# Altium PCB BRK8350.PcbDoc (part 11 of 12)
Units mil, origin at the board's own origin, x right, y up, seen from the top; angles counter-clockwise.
Board outline 9448.82 x 5905.51 mil, 8 copper layers (L1-TOP, L2-GND, L3-SIG, L4-GND, L5-PWR, L6-PWR, L7-GND, L8-BOT), stack 57.69 mil thick; 288 components, 543 nets, 1891 pads, 2032 vias.
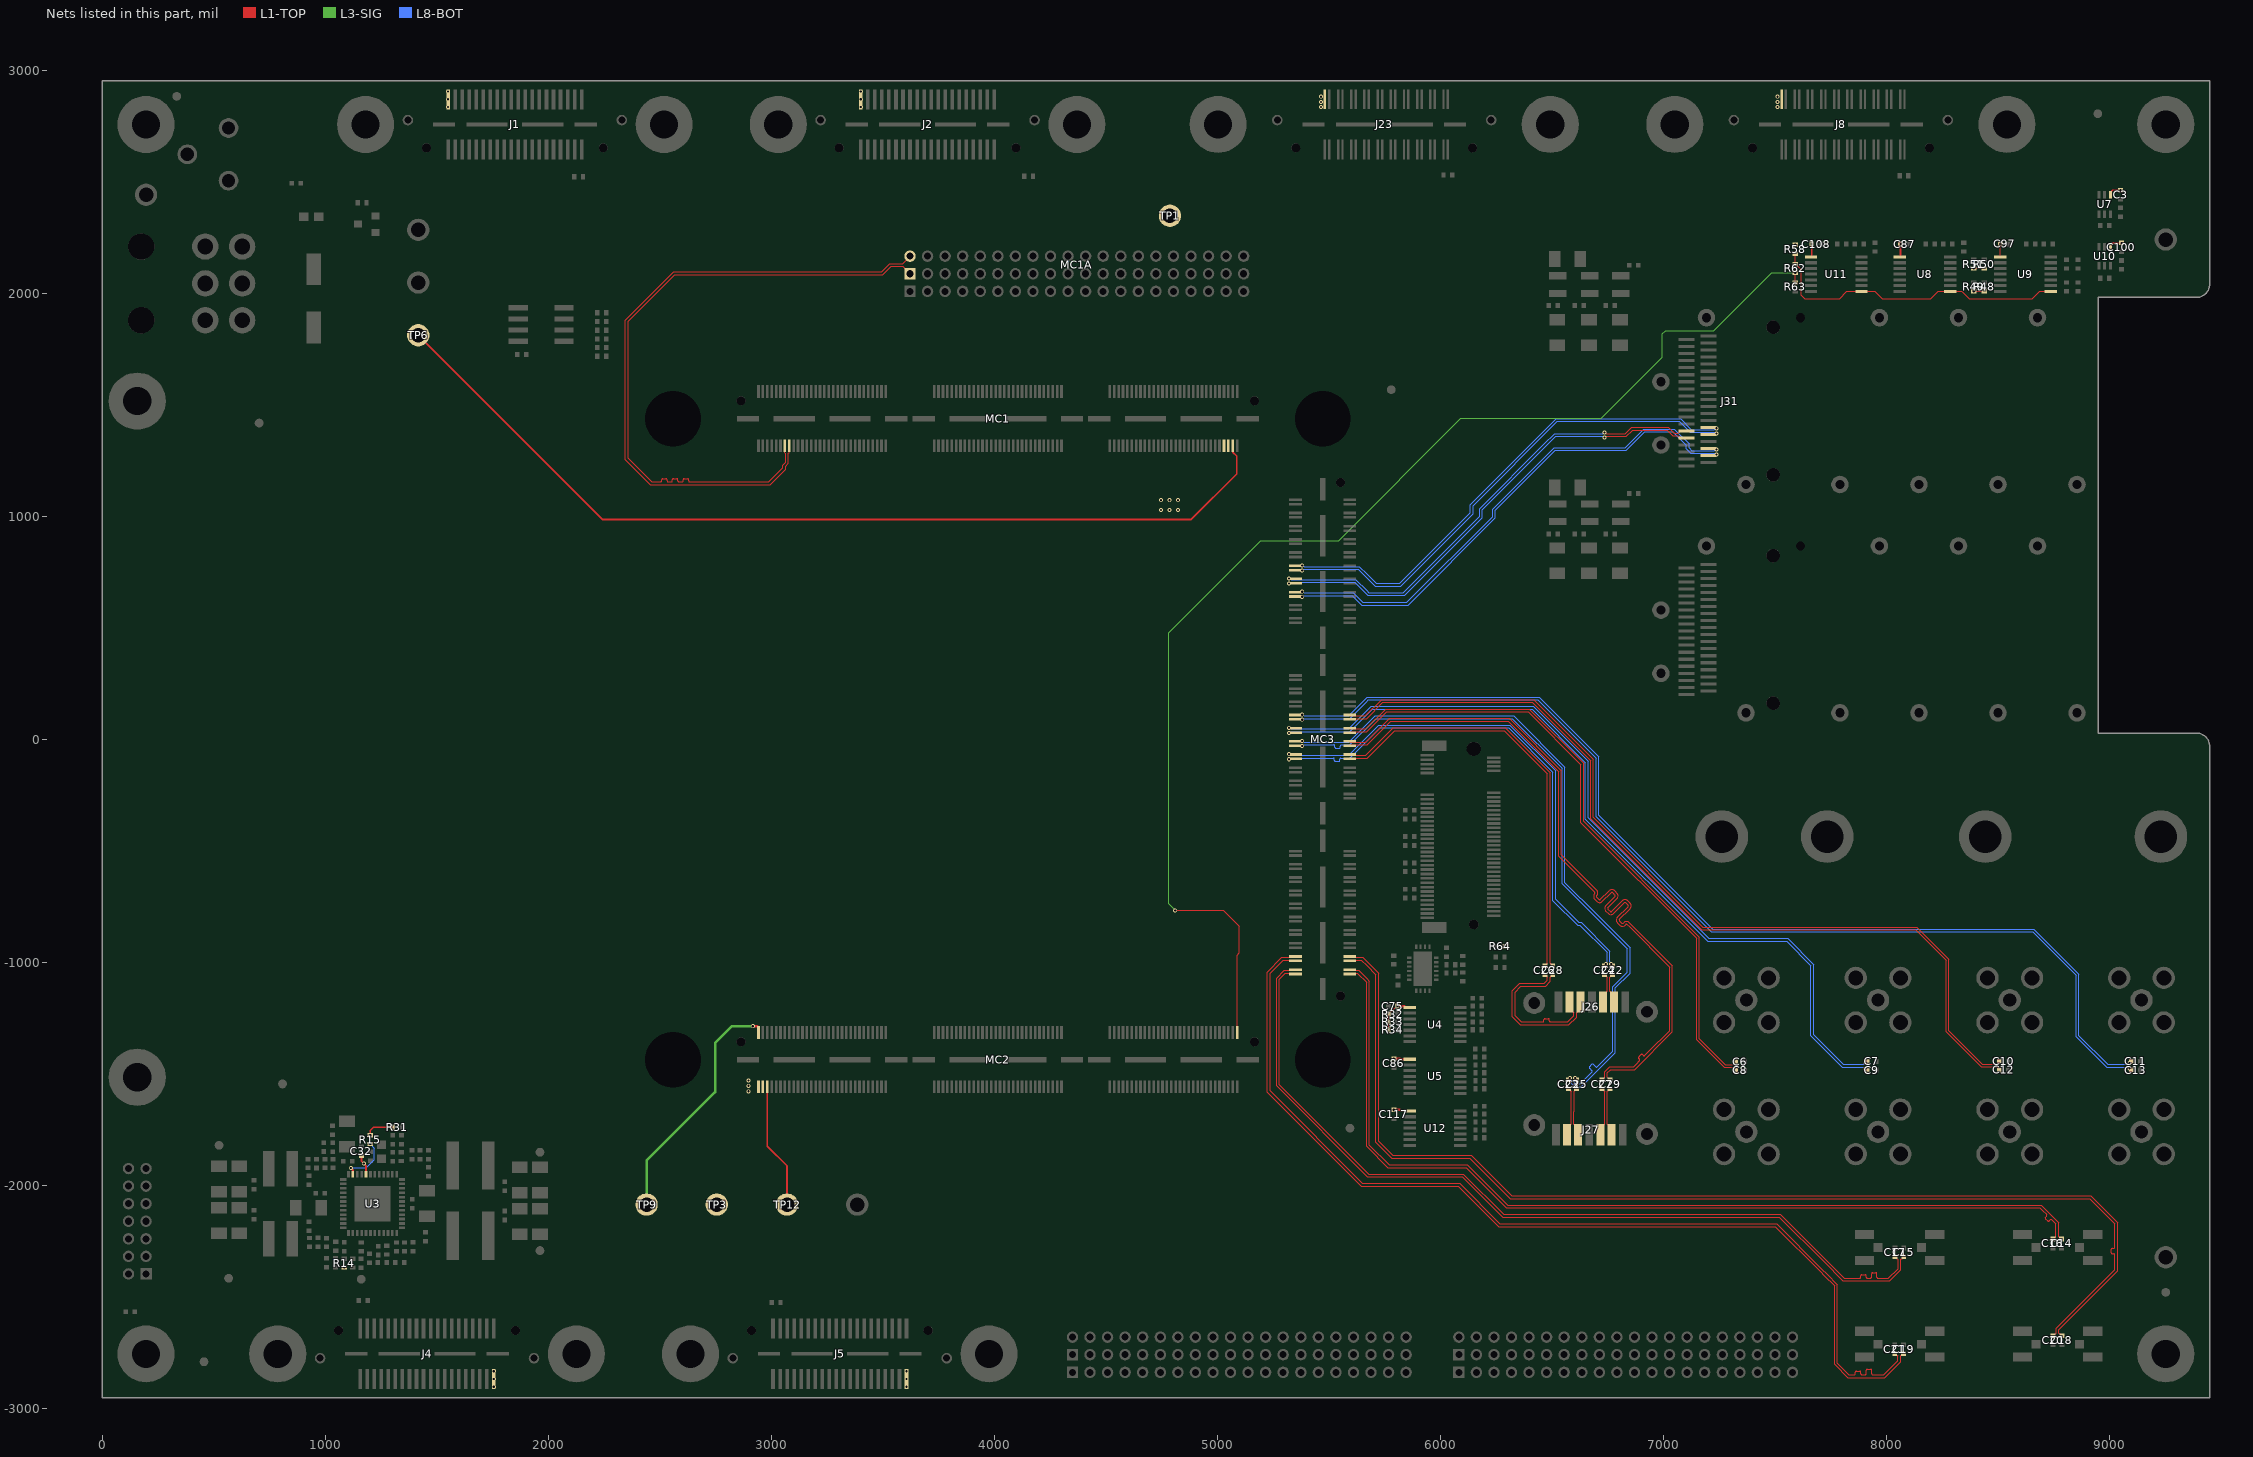
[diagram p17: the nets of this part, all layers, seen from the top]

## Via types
v1: diameter 18, hole 10, L1-TOP to L8-BOT, tented both sides, 2032 vias

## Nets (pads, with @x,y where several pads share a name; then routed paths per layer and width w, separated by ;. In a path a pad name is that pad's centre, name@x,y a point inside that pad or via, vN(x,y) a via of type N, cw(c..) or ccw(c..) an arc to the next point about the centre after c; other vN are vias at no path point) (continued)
QSFP_2_TX2N: J31.2 MC3.32 | length 2270.6
  L8-BOT w4.2: v1(5380.17,638.28) 5383.91,638.28 5388.95,643.32 5604.51,643.32 5646.95,600.88 5855.09,600.88 6246.95,992.73 6246.95,1026.21 6515.22,1294.49 6833.86,1294.49 6917.32,1377.95 7042.75,1377.95 7102.5,1318.21 7102.5,1301.41 7122.81,1281.1 7228.34,1281.1 7233.68,1275.76 v1(7237.42,1275.76)
QSFP_2_TX2P: J31.3 MC3.30 | length 2270.6
  L8-BOT w4.2: v1(5380.17,660.96) 5383.91,660.96 5388.95,655.92 5609.73,655.92 5652.17,613.48 5849.87,613.48 6234.35,997.95 6234.35,1031.43 6510,1307.09 6828.64,1307.09 6912.1,1390.55 7047.97,1390.55 7115.1,1323.43 7115.1,1306.63 7128.03,1293.7 7228.34,1293.7 7233.68,1299.05 v1(7237.42,1299.05)
QSFP_2_TX3N: J31.34 MC3.28 | length 2155.9
  L1-TOP w4.2: v1(6736.22,1352.53) 6739.14,1352.53 6744.09,1357.48 6833.86,1357.48 6862.2,1385.83 7016.61,1385.83 7042.6,1359.84 7067.34,1359.84 7069.8,1357.38 7069.8,1355.18 7074.59,1350.39 J31.34@7103.13,1350.39
  L8-BOT w4.2: v1(5321.43,697.33) 5325.17,697.33 5330.21,702.38 5616.32,702.38 5669.29,649.4 5674.51,644.18 5839.29,644.18 6188.26,993.16 6188.26,1028.65 6517.09,1357.48 6727.54,1357.48 6732.49,1352.53 v1(6736.22,1352.53)
QSFP_2_TX3P: J31.33 MC3.26 | length 2155.9
  L1-TOP w4.2: v1(6736.22,1375.03) 6739.14,1375.03 6744.09,1370.08 6828.64,1370.08 6856.99,1398.43 7021.83,1398.43 7047.82,1372.44 7067.34,1372.44 7069.8,1374.9 7069.8,1377.1 7074.59,1381.89 J31.33@7103.13,1381.89
  L8-BOT w4.2: v1(5321.43,720.02) 5325.17,720.02 5330.21,714.98 5621.54,714.98 5669.29,667.22 5679.73,656.78 5834.07,656.78 6175.66,998.38 6175.66,1033.87 6465.12,1323.33 6511.87,1370.08 6727.54,1370.08 6732.49,1375.03 v1(6736.22,1375.03)
QSFP_2_TX4N: J31.5 MC3.24 | length 2239.7
  L8-BOT w4.2: v1(5380.17,756.39) 5383.91,756.39 5388.95,761.43 5632.07,761.43 5669.29,724.21 5707.51,685.98 5821.97,685.98 6146.46,1010.47 6146.46,1045.96 6524.9,1424.41 7071.66,1424.41 7120.47,1375.59 7228.34,1375.59 7233.68,1370.24 v1(7237.42,1370.24)
QSFP_2_TX4P: J31.6 MC3.22 | length 2239.7
  L8-BOT w4.2: v1(5380.17,779.07) 5383.91,779.07 5388.95,774.03 5637.28,774.03 5669.29,742.03 5712.73,698.58 5816.75,698.58 6133.86,1015.69 6133.86,1051.18 6519.69,1437.01 7076.87,1437.01 7125.69,1388.19 7228.34,1388.19 7233.68,1393.54 v1(7237.42,1393.54)
QSFP_THREESTATE#: R58.1 R62.2 U8.8 U9.8 U11.8 | length 1393.5
  L1-TOP w5: R58.1@7590.55,2177.17 R62.2@7590.55,2129.92 7592.52,2129.92 7617.49,2104.95 7617.49,1990.78 7633.86,1974.41 7789.37,1974.41 7822.83,2007.87 U11.8@7887.8,2007.87 7947.43,2007.87 7980.89,1974.41 8198.82,1974.41 8232.28,2007.87 U8.8@8285.43,2007.87 8338.58,2007.87 8372.05,1974.41 8653.54,1974.41 8687.01,2007.87 U9.8@8736.22,2007.87
QSFP_THREESTATE_N_IO: MC2.179 R62.1 R63.2 | length 5635.9
  L1-TOP w5: v1(4811.02,-767.72) 5027.06,-767.72 5098.43,-839.09 5098.43,-958.37 5088.6,-968.19 5088.6,-1240.16 MC2.179@5088.6,-1315.34 ; R63.2@7590.55,2047.24 v1(7590.55,2090.55)
  L3-SIG w5: v1(4811.02,-767.72) 4782.17,-738.86 4782.17,477.84 5194.09,889.76 5544.24,889.76 6092.29,1437.81 6720.98,1437.81 6995.26,1712.09 6995.26,1816.92 7009.37,1831.03 7225.91,1831.03 7485.43,2090.55 v1(7590.55,2090.55)
SATA_1_RXB+: C28.2 MC3.65 | length 1905.5
  L1-TOP w4.2: MC3.65@5594.11,-68.88 5597.65,-72.42 5665.78,-72.42 5789.25,51.05 6291.41,51.05 6300.32,42.14 6492.52,-150.06 6492.52,-989.23 6492.52,-1005.45 6494.98,-1007.91 6495.8,-1007.91 C28.2@6503.94,-1016.05
SATA_1_RXB+_C: C28.1 J26.6 | length 696.2
  L1-TOP w4.2: C28.1@6503.94,-1056.2 6495.8,-1064.34 6494.98,-1064.34 6492.52,-1066.8 6492.52,-1086.49 6471.67,-1107.33 6361.17,-1107.33 6334.65,-1133.86 6334.65,-1240.16 6362.2,-1267.72 6420.67,-1267.72 6459.5,-1267.72 ccw(c6459.5,-1262.88) 6464.34,-1262.88 6464.34,-1257.68 cw(c6469.18,-1257.68) 6469.18,-1252.84 6483.7,-1252.84 cw(c6483.7,-1257.68) 6488.54,-1257.68 6488.54,-1262.88 ccw(c6493.38,-1262.88) 6493.38,-1267.72 6519.69,-1267.72 6570.87,-1267.72 6597.64,-1240.95 6597.64,-1226.74 6595.18,-1224.28 6594.55,-1224.28 6578.94,-1208.66 J26.6@6578.94,-1179.13
SATA_1_RXB-: C26.2 MC3.67 | length 1884.6
  L1-TOP w4.2: MC3.67@5594.11,-88.57 5597.65,-85.02 5671,-85.02 5794.47,38.45 6286.19,38.45 6479.92,-155.28 6479.92,-876.28 6479.92,-984.01 6479.92,-1005.45 6477.46,-1007.91 6476.64,-1007.91 C26.2@6468.5,-1016.05
SATA_1_RXB-_C: C26.1 J26.5 | length 716.5
  L1-TOP w4.2: C26.1@6468.5,-1056.2 6476.64,-1064.34 6477.46,-1064.34 6479.92,-1066.8 6479.92,-1081.27 6466.45,-1094.73 6355.95,-1094.73 6322.05,-1128.64 6322.05,-1245.38 6356.99,-1280.32 6576.09,-1280.32 6610.24,-1246.16 6610.24,-1226.74 6612.7,-1224.28 6613.32,-1224.28 6628.94,-1208.66 J26.5@6628.94,-1179.13
SATA_1_TXA+: C22.2 MC3.66 | length 2313.4
  L8-BOT w4.2: v1(5321.43,-67.38) 5325.17,-67.38 5330.21,-72.42 5574.1,-72.42 5589.11,-72.42 5724.38,62.84 6311.11,62.84 6320.02,53.93 6516.54,-142.58 6516.54,-663.78 6516.54,-718.31 6620.08,-821.85 6631.01,-821.85 6760.04,-950.88 6760.04,-998.66 6765.74,-1004.36 v1(6765.74,-1008.02)
SATA_1_TXA+_C: C22.1 J26.2 | length 138.2
  L1-TOP w4.2: C22.1@6773.74,-1054.24 6760.24,-1067.74 6760.24,-1130.62 6778.94,-1149.32 J26.2@6778.94,-1179.13
SATA_1_TXA-: C24.2 MC3.68 | length 2314.1
  L8-BOT w4.2: v1(5321.43,-90.07) 5325.17,-90.07 5330.21,-85.02 5493.94,-85.02 5520.24,-85.02 cw(c5520.24,-89.86) 5525.08,-89.86 5525.08,-95.16 ccw(c5529.92,-95.16) 5529.92,-100 5544.44,-100 ccw(c5544.44,-95.16) 5549.28,-95.16 5549.28,-89.86 cw(c5554.12,-89.86) 5554.12,-85.02 5574.1,-85.02 5594.33,-85.02 5729.6,50.24 6305.9,50.24 6503.94,-147.8 6503.94,-723.53 6614.86,-834.45 6625.79,-834.45 6747.44,-956.1 6747.44,-998.66 6741.74,-1004.36 v1(6741.74,-1008.02)
SATA_1_TXA-_C: C24.1 J26.3 | length 138.4
  L1-TOP w4.2: J26.3@6728.94,-1179.13 6728.94,-1148.93 6747.64,-1130.23 6747.64,-1068.13 C24.1@6733.74,-1054.24
SATA_2_RXB+: C29.2 MC3.61 | length 3198.4
  L1-TOP w4.2: MC3.61@5594.11,-9.83 5597.65,-13.37 5665.72,-13.37 5771.94,92.85 6308.73,92.85 6317.64,83.94 6542.59,-141.01 6542.59,-518.97 6680.67,-657.05 6700.56,-676.94 ; 6700.58,-676.96 6702.41,-678.78 6702.41,-679.11 cw(c6688.23,-689.27) 6700.56,-701.6 ccw(c6703.98,-705.03) 6700.56,-708.45 6710.83,-718.72 ccw(c6714.25,-715.29) 6717.67,-718.71 6756.5,-679.89 cw(c6768.83,-692.22) 6778.99,-678.04 6779.32,-678.04 6781.14,-679.86 ; C29.2@6760.45,-1527.17 6752.31,-1519.03 6751.49,-1519.03 6749.03,-1516.57 6749.03,-1507.48 6749.03,-1496.06 6763.99,-1481.1 6871.36,-1481.1 7040.16,-1312.31 7040.16,-1016.54 6852.36,-828.74 6846.42,-822.8 6844.58,-820.95 6844.25,-820.95 ccw(c6834.09,-835.13) 6821.76,-822.8 6819.83,-824.72 cw(c6816.41,-821.3) 6812.99,-824.72 6802.72,-814.46 cw(c6806.15,-811.03) 6802.7,-807.63 6850.31,-760.02 ccw(c6837.98,-747.69) 6852.16,-737.54 6852.15,-737.21 6850.33,-735.38 6840.04,-725.09 ; 6781.16,-679.89 6791.43,-690.15 ; 6791.45,-690.18 6793.28,-692 6793.28,-692.33 cw(c6779.1,-702.49) 6791.43,-714.82 6750.66,-755.59 ccw(c6754.1,-758.99) 6750.68,-762.41 6760.95,-772.68 ccw(c6764.37,-769.26) 6767.79,-772.68 6815.35,-725.12 ; 6815.38,-725.09 cw(c6827.71,-737.43) 6837.87,-723.25 6838.2,-723.25 6840.02,-725.07
SATA_2_RXB+_C: C29.1 J27.6 | length 219.7
  L1-TOP w4.2: C29.1@6760.45,-1567.32 6752.31,-1575.46 6751.49,-1575.46 6749.03,-1577.92 6749.03,-1639.75 6748.82,-1639.96 6748.82,-1726.02 6751.28,-1728.48 6751.9,-1728.48 6767.52,-1744.09 J27.6@6767.52,-1773.62
SATA_2_RXB-: C27.2 MC3.63 | length 3197.6
  L1-TOP w4.2: MC3.63@5594.11,-29.51 5597.65,-25.97 5670.94,-25.97 5777.16,80.25 6303.51,80.25 6529.99,-146.23 6529.99,-524.19 6671.76,-665.96 6691.62,-685.82 cw(c6688.23,-689.27) 6691.65,-692.69 6691.61,-692.74 ccw(c6703.98,-705.03) 6691.65,-717.36 6701.92,-727.62 ccw(c6714.25,-715.29) 6726.58,-727.62 6765.41,-688.8 cw(c6768.83,-692.22) 6772.27,-688.82 6782.49,-699.03 ; C27.2@6725.01,-1527.17 6733.15,-1519.03 6733.97,-1519.03 6736.43,-1516.57 6736.43,-1502.26 6736.43,-1490.84 6758.77,-1468.5 6866.14,-1468.5 6882.63,-1452.01 6892.47,-1442.18 ccw(c6889.04,-1438.76) 6892.47,-1435.33 6889.12,-1431.99 cw(c6892.55,-1428.57) 6889.12,-1425.15 6899.39,-1414.88 cw(c6902.81,-1418.3) 6906.24,-1414.88 6909.58,-1418.22 ccw(c6913,-1414.8) 6916.42,-1418.22 6935.02,-1399.62 7027.56,-1307.09 7027.56,-1021.76 6843.45,-837.65 6837.55,-831.74 ; 6741.77,-746.66 ccw(c6754.1,-758.99) 6741.77,-771.32 6752.04,-781.59 ccw(c6764.37,-769.26) 6776.7,-781.59 6824.31,-733.98 cw(c6827.71,-737.43) 6831.15,-734.02 6841.37,-744.24 cw(c6837.98,-747.69) 6841.4,-751.12 6793.84,-798.68 ccw(c6806.15,-811.03) 6793.81,-823.37 6804.08,-833.63 ccw(c6816.41,-821.3) 6828.74,-833.63 6830.67,-831.71 cw(c6834.09,-835.13) 6837.53,-831.73 ; 6741.8,-746.63 6782.52,-705.91 ccw(c6779.1,-702.49) 6782.5,-699.04
SATA_2_RXB-_C: C27.1 J27.5 | length 219.7
  L1-TOP w4.2: J27.5@6717.52,-1773.62 6717.52,-1744.09 6733.14,-1728.48 6733.76,-1728.48 6736.22,-1726.02 6736.22,-1634.74 6736.43,-1634.53 6736.43,-1577.92 6733.97,-1575.46 6733.15,-1575.46 C27.1@6725.01,-1567.32
SATA_2_TXA+: C23.2 MC3.62 | length 3046.2
  L8-BOT w4.2: v1(5380.17,-8.33) 5383.91,-8.33 5388.95,-13.37 5582.5,-13.37 5589.05,-13.37 5707.06,104.64 6328.43,104.64 6337.34,95.73 6558.34,-125.27 6558.34,-642.88 6701.44,-785.98 6841.48,-926.03 6850.39,-934.94 6850.39,-1049.32 6784.25,-1115.46 6784.25,-1405.51 6631.85,-1557.92 6601.84,-1557.92 6586.02,-1542.1 6586.02,-1528.49 6580.32,-1522.79 v1(6580.32,-1519.13)
SATA_2_TXA+_C: C23.1 J27.2 | length 219.7
  L1-TOP w4.2: J27.2@6567.52,-1773.62 6567.52,-1744.09 6583.14,-1728.48 6583.76,-1728.48 6586.22,-1726.02 6586.22,-1664.28 6586.43,-1664.07 6586.43,-1577.92 6583.97,-1575.46 6583.15,-1575.46 C23.1@6575.01,-1567.32
SATA_2_TXA-: C25.2 MC3.64 | length 3045.9
  L8-BOT w4.2: v1(5380.17,-31.01) 5383.91,-31.01 5388.95,-25.97 5496.06,-25.97 5522.36,-25.97 cw(c5522.36,-30.81) 5527.2,-30.81 5527.2,-35.87 ccw(c5532.04,-35.87) 5532.04,-40.71 5546.56,-40.71 ccw(c5546.56,-35.87) 5551.4,-35.87 5551.4,-30.81 cw(c5556.24,-30.81) 5556.24,-25.97 5582.5,-25.97 5594.27,-25.97 5712.28,92.04 6323.21,92.04 6545.74,-130.49 6545.74,-648.1 6696.22,-798.58 6837.79,-940.16 6837.79,-1044.1 6771.65,-1110.24 6771.65,-1400.29 6721.8,-1450.15 6703.2,-1468.74 cw(c6699.78,-1465.32) 6696.36,-1468.74 6685.73,-1458.12 ccw(c6682.31,-1461.54) 6678.89,-1458.12 6668.62,-1468.39 ccw(c6672.04,-1471.81) 6668.62,-1475.23 6679.25,-1485.86 cw(c6675.82,-1489.28) 6679.25,-1492.7 6670.62,-1501.33 6626.63,-1545.32 6607.06,-1545.32 6598.62,-1536.88 6598.62,-1528.49 6604.32,-1522.79 v1(6604.32,-1519.13)
SATA_2_TXA-_C: C25.1 J27.3 | length 219.7
  L1-TOP w4.2: C25.1@6610.45,-1567.32 6602.31,-1575.46 6601.49,-1575.46 6599.03,-1577.92 6599.03,-1669.29 6598.82,-1669.5 6598.82,-1726.02 6601.28,-1728.48 6601.9,-1728.48 6617.52,-1744.09 J27.3@6617.52,-1773.62
SMA_RXN0: C8.2 MC3.59 | length 2855
  L1-TOP w4.2: MC3.59@5594.11,29.54 5597.65,33.09 5670.88,33.09 5759.84,122.05 6394.08,122.05 6629.92,-113.79 6629.92,-374.02 7148.82,-892.91 7148.82,-1347.74 7272.96,-1471.88 7314.11,-1471.88 7316.57,-1474.35 7316.57,-1476.95 C8.2@7324.7,-1485.08
SMA_RXN1: C12.2 MC3.55 | length 3968.3
  L1-TOP w4.2: MC3.55@5594.11,88.6 5597.65,92.14 5669.02,92.14 5741.59,164.72 6412.33,164.72 6673,-95.95 6673,-356.17 7171.95,-855.12 8130.71,-855.12 8266.93,-991.34 8266.93,-1312.72 8423.91,-1469.71 8495.59,-1469.71 8498.05,-1472.17 8498.05,-1474.78 C12.2@8506.18,-1482.91
SMA_RXP0: C6.2 MC3.57 | length 2855
  L1-TOP w4.2: MC3.57@5594.11,49.23 5597.65,45.69 5665.66,45.69 5754.62,134.65 6399.3,134.65 6642.52,-108.57 6642.52,-368.8 7161.42,-887.69 7161.42,-1342.52 7278.18,-1459.28 7314.11,-1459.28 7316.57,-1456.82 7316.57,-1454.22 C6.2@7324.7,-1446.08
SMA_RXP1: C10.2 MC3.53 | length 3968.3
  L1-TOP w4.2: MC3.53@5594.11,108.28 5597.65,104.74 5663.8,104.74 5736.38,177.32 6417.55,177.32 6685.6,-90.73 6685.6,-350.95 7177.17,-842.52 8135.93,-842.52 8279.53,-986.12 8279.53,-1307.51 8429.13,-1457.11 8495.59,-1457.11 8498.05,-1454.65 8498.05,-1452.05 C10.2@8506.18,-1443.91
SMA_TXN0: C9.2 MC3.60 | length 3628.1
  L8-BOT w4.2: v1(5321.43,28.04) 5325.17,28.04 5330.21,33.09 5594.21,33.09 5694.97,133.84 6410.89,133.84 6649.61,-104.87 6649.61,-358.12 7197.79,-906.3 7551.97,-906.3 7661.42,-1015.75 7661.42,-1330.71 7801.48,-1470.77 7883.32,-1470.77 7897.06,-1470.77 7902.32,-1476.02 v1(7906.05,-1476.02)
SMA_TXN1: C13.2 MC3.56 | length 4745.6
  L8-BOT w4.2: v1(5380.17,87.1) 5383.91,87.1 5388.95,92.14 5594.21,92.14 5669.29,167.22 5669.29,167.28 5677.66,175.64 6437.32,175.64 6697.85,-84.89 6697.85,-347.25 7215.11,-864.5 8655.84,-864.5 8850.39,-1059.06 8850.39,-1334.65 8986.51,-1470.77 9067.05,-1470.77 9080.79,-1470.77 9086.05,-1476.02 v1(9089.78,-1476.02)
SMA_TXP0: C7.2 MC3.58 | length 3628.1
  L8-BOT w4.2: v1(5321.43,50.73) 5325.17,50.73 5330.21,45.69 5588.99,45.69 5689.75,146.44 6416.11,146.44 6662.21,-99.65 6662.21,-352.9 7203.01,-893.7 7557.19,-893.7 7674.02,-1010.53 7674.02,-1325.49 7806.69,-1458.17 7888.54,-1458.17 7897.06,-1458.17 7902.32,-1452.91 v1(7906.05,-1452.91)
SMA_TXP1: C11.2 MC3.54 | length 4745.6
  L8-BOT w4.2: v1(5380.17,109.78) 5383.91,109.78 5388.95,104.74 5588.99,104.74 5656.69,172.44 5656.69,172.5 5672.44,188.24 6442.54,188.24 6710.45,-79.67 6710.45,-342.03 7220.32,-851.9 8661.06,-851.9 8862.99,-1053.84 8862.99,-1329.43 8991.73,-1458.17 9072.27,-1458.17 9080.79,-1458.17 9086.05,-1452.91 v1(9089.78,-1452.91)
SUPPLY_1_CE: R15.1 U3.23 | length 231.9
  L1-TOP w8: v1(1114.74,-1922.66) 1124.16,-1932.08 U3.23@1124.16,-1950.77
  L8-BOT w5: v1(1114.74,-1922.66) 1183.51,-1922.66 1220.91,-1885.26 1220.91,-1833.67 v1(1202.1,-1814.85)
UFL_RXN0: C16.2 MC3.119 | length 4162.6
  L1-TOP w4.2: MC3.119@5594.11,-1053.13 5597.65,-1049.59 5628.33,-1049.59 5669.29,-1090.55 5669.29,-1824.96 5764.87,-1920.54 6115.26,-1920.54 6296.36,-2101.64 8688.26,-2101.64 8699.1,-2112.48 8717.7,-2131.08 cw(c8714.27,-2134.5) 8717.7,-2137.93 8712.81,-2142.81 ccw(c8716.23,-2146.24) 8712.81,-2149.66 8723.08,-2159.93 ccw(c8726.5,-2156.5) 8729.92,-2159.93 8734.81,-2155.04 cw(c8738.23,-2158.46) 8741.65,-2155.04 8755.91,-2169.29 8759.42,-2172.8 8759.42,-2230.48 8756.96,-2232.94 8754.17,-2232.94 C16.2@8746.03,-2241.08
UFL_RXN1: C20.2 MC3.115 | length 5001.9
  L1-TOP w4.2: MC3.115@5594.11,-994.08 5597.65,-990.54 5645.95,-990.54 5669.29,-1013.88 5711.09,-1055.68 5711.09,-1807.65 5782.18,-1878.74 6132.58,-1878.74 6313.68,-2059.84 8911.09,-2059.84 9023.62,-2172.38 9023.62,-2251.97 9023.62,-2278.27 cw(c9018.78,-2278.27) 9018.78,-2283.11 9012.87,-2283.11 ccw(c9012.87,-2287.95) 9008.03,-2287.95 9008.03,-2302.47 ccw(c9012.87,-2302.47) 9012.87,-2307.31 9018.78,-2307.31 cw(c9018.78,-2312.15) 9023.62,-2312.15 9023.62,-2326.77 9023.62,-2378.67 8760.42,-2641.88 8760.42,-2647.7 8760.42,-2663.55 8757.96,-2666.01 8755.17,-2666.01 C20.2@8747.03,-2674.15
UFL_RXP0: C14.2 MC3.117 | length 4158.6
  L1-TOP w4.2: MC3.117@5594.11,-1033.45 5597.65,-1036.99 5633.55,-1036.99 5669.29,-1072.73 5681.89,-1085.33 5681.89,-1819.75 5770.09,-1907.94 6120.48,-1907.94 6301.58,-2089.04 8693.48,-2089.04 8708.01,-2103.58 8772.02,-2167.58 8772.02,-2230.48 8774.48,-2232.94 8777.27,-2232.94 C14.2@8785.4,-2241.08
UFL_RXP1: C18.2 MC3.113 | length 4999.9
  L1-TOP w4.2: MC3.113@5594.11,-974.39 5597.65,-977.94 5651.16,-977.94 5669.29,-996.06 5723.69,-1050.46 5723.69,-1802.43 5787.4,-1866.14 6137.8,-1866.14 6146.7,-1875.05 6318.9,-2047.24 8698.19,-2047.24 8916.31,-2047.24 9036.22,-2167.16 9036.22,-2251.97 9036.22,-2383.89 8773.02,-2647.1 8773.02,-2652.92 8773.02,-2663.55 8775.48,-2666.01 8778.27,-2666.01 C18.2@8786.4,-2674.15
UFL_TXN0: C17.2 MC3.120 | length 3833.3
  L1-TOP w4.2: MC3.120@5350.8,-1053.13 5347.26,-1049.59 5304.74,-1049.59 5277.89,-1076.45 5277.89,-1549.54 5678.09,-1949.74 6103.17,-1949.74 6284.27,-2130.84 7524.54,-2130.84 7810.23,-2416.53 7830.71,-2416.53 7879.61,-2416.53 ccw(c7879.61,-2411.69) 7884.45,-2411.69 7884.45,-2405.75 cw(c7889.29,-2405.75) 7889.29,-2400.91 7903.81,-2400.91 cw(c7903.81,-2405.75) 7908.65,-2405.75 7908.65,-2411.69 ccw(c7913.49,-2411.69) 7913.49,-2416.53 7928.01,-2416.53 ccw(c7928.01,-2411.69) 7932.85,-2411.69 7932.85,-2396.37 cw(c7937.69,-2396.37) 7937.69,-2391.53 7952.21,-2391.53 cw(c7952.21,-2396.37) 7957.05,-2396.37 7957.05,-2411.69 ccw(c7961.89,-2411.69) 7961.89,-2416.53 7988.19,-2416.53 8008.66,-2416.53 8051.76,-2373.44 8051.76,-2331.99 8049.29,-2329.53 8046.51,-2329.53 C17.2@8038.37,-2321.39
UFL_TXN1: C21.2 MC3.116 | length 4348.1
  L1-TOP w4.2: MC3.116@5350.8,-994.08 5347.26,-990.54 5295,-990.54 5236.09,-1049.45 5236.09,-1577.37 5650.26,-1991.54 6085.85,-1991.54 6266.96,-2172.64 7507.23,-2172.64 7710.81,-2376.22 7732.04,-2397.45 7780.32,-2445.73 7780.32,-2798.15 7831.77,-2849.6 7834.65,-2849.6 7855.99,-2849.6 ccw(c7855.99,-2844.76) 7860.83,-2844.76 7860.83,-2837.82 cw(c7865.67,-2837.82) 7865.67,-2832.98 7880.19,-2832.98 cw(c7880.19,-2837.82) 7885.03,-2837.82 7885.03,-2844.76 ccw(c7889.87,-2844.76) 7889.87,-2849.6 7904.39,-2849.6 ccw(c7904.39,-2844.76) 7909.23,-2844.76 7909.23,-2829.44 cw(c7914.07,-2829.44) 7914.07,-2824.6 7928.59,-2824.6 cw(c7928.59,-2829.44) 7933.43,-2829.44 7933.43,-2844.76 ccw(c7938.27,-2844.76) 7938.27,-2849.6 7964.57,-2849.6 7986.91,-2849.6 8050.76,-2785.76 8050.76,-2765.06 8048.29,-2762.6 8045.51,-2762.6 C21.2@8037.37,-2754.46
UFL_TXP0: C15.2 MC3.118 | length 3831.3
  L1-TOP w4.2: MC3.118@5350.8,-1033.45 5347.26,-1036.99 5299.52,-1036.99 5265.29,-1071.23 5265.29,-1554.76 5672.87,-1962.34 6097.95,-1962.34 6279.05,-2143.44 7519.33,-2143.44 7717.68,-2341.8 7805.02,-2429.13 7830.71,-2429.13 8013.88,-2429.13 8064.36,-2378.66 8064.36,-2331.99 8066.82,-2329.53 8069.6,-2329.53 C15.2@8077.74,-2321.39
UFL_TXP1: C19.2 MC3.114 | length 4344.1
  L1-TOP w4.2: MC3.114@5350.8,-974.39 5347.26,-977.94 5289.78,-977.94 5223.49,-1044.23 5223.49,-1582.58 5645.04,-2004.14 6080.63,-2004.14 6261.74,-2185.24 7502.01,-2185.24 7705.59,-2388.82 7719.44,-2402.67 7767.72,-2450.95 7767.72,-2803.37 7826.55,-2862.2 7834.65,-2862.2 7992.13,-2862.2 8063.36,-2790.98 8063.36,-2765.06 8065.82,-2762.6 8068.6,-2762.6 C19.2@8076.74,-2754.46
VCCBATT: MC2.6 TP12.1 | length 564.6
  L1-TOP w8: MC2.6@2982.3,-1558.65 2982.3,-1611.8 2982.3,-1824.82 3070.74,-1913.26 TP12.1@3070.74,-2086.61
VDDD: C32.2 R14.2 R15.2 R31.2 U3.20 | length 220.4
  L1-TOP w8: C32.2@1162.74,-1866.74 1162.74,-1891.7 1183.21,-1912.17 U3.20@1183.21,-1950.77 ; v1(1202.1,-1775.48) 1202.1,-1754.6 1216.54,-1740.16 R31.2@1303.15,-1740.16
  other v1: 1085.74,-2368.85 1172.98,-1901.93
VIO1: J1.39 J2.39 J8.39 J23.39 MC1.174 MC1.176 TP1.1
  other v1: 4746.91,1028 4785.23,1028 4823.55,1028 4746.91,1071.31 4785.23,1071.31 4823.55,1071.31 1551.24,2833.71 3401.64,2833.71 5464.68,2833.67 7511.92,2833.67 5464.68,2856.67 7511.92,2856.67 1551.24,2868.71 3401.64,2868.71 5464.68,2880.67 7511.92,2880.67 1551.24,2903.71 3401.64,2903.71
VIO2: C3.2 C75.2 C86.2 C87.2 C97.2 C100.2 C108.2 C117.2 J4.39 J5.39 MC2.2 MC2.4 R32.2 R33.2 R34.2 R48.2 R49.2 R50.2 R51.2 R58.2 R64.2 TP3.1 U4.1 U5.1 U7.1 U8.1 U9.1 U10.1 U11.1 U12.1 | length 722.3
  L1-TOP w5: R34.2@5767.72,-1303.15 R33.2@5767.72,-1267.72 5767.72,-1230.31 5774.06,-1223.97 5776.82,-1223.97 5796.62,-1204.18 5800.74,-1204.18 5807.48,-1197.44 v1(5807.48,-1196.85) ; v1(8391.5,2007.98) R48.2@8438.74,2007.98 ; v1(8391.5,2110.35) R50.2@8438.74,2110.35 ; v1(8509.21,2220.58) 8509.21,2162.05 U9.1@8509.84,2161.42
  L1-TOP w8: U11.1@7661.42,2161.42 7661.81,2161.42 7664.7,2164.31 C108.2@7664.7,2225.62 ; U8.1@8059.06,2161.42 8059.45,2161.42 8062.34,2164.31 v1(8062.34,2219.65) ; U7.1@9003.94,2440.94 9003.94,2450.79 9014.17,2461.02 v1(9049.21,2461.02)
  L1-TOP w10: v1(5791.34,-1661.02) 5818.5,-1661.02 5824.8,-1667.32 U12.1@5863.19,-1667.32 ; 5802.17,-1432.68 5819.45,-1432.68 5821.81,-1435.04 U5.1@5863.19,-1435.04 ; U10.1@9003.94,2208.66 9003.94,2218.5 9005.83,2220.39 9007.28,2220.39 9011.68,2224.8 v1(9053.15,2224.8)
  L1-TOP w11: v1(5807.48,-1196.85) 5836.61,-1196.85 5842.52,-1202.76 U4.1@5863.19,-1202.76 U4.1@5863.43,-1202.52
  other v1: 1755.94,-2903.71 3606.34,-2903.71 1755.94,-2868.71 3606.34,-2868.71 1755.94,-2833.71 3606.34,-2833.71 2897.64,-1578.74 2897.64,-1554.42 2897.64,-1530.1 5791.34,-1432.68 6287.4,-929.13 7590.55,2216.54 7664.7,2219.62
VREF1: MC1.178 TP6.1 | length 4229.5
  L1-TOP w8: TP6.1@1417.32,1811.02 2243.11,985.24 4882.87,985.24 5086.61,1188.98 5086.61,1269.54 5068.91,1287.25 MC1.178@5068.91,1315.37
VREF2: MC2.1 TP9.1 | length 1102.8
  L1-TOP w11: v1(2917.32,-1286.8) 2937.02,-1286.8 2942.93,-1292.7 MC2.1@2942.93,-1315.34
  L3-SIG w11: TP9.1@2440.94,-2086.61 2440.94,-1889.76 2748.03,-1582.68 2748.03,-1362.2 2823.44,-1286.8 v1(2917.32,-1286.8)
XADC_VN: MC1.16 MC1A.2 | length 2926.4
  L1-TOP w4.2: MC1.16@3080.72,1315.37 3080.72,1284.73 3077.18,1281.18 3077.18,1236.59 3064.5,1223.9 3064.5,1210.65 2994.79,1140.94 2458.23,1140.94 2345.67,1253.51 2345.67,1879.23 2561.71,2095.28 3494.78,2095.28 3531.79,2132.28 3588.98,2132.28 MC1A.2@3622.05,2165.35
XADC_VP: MC1.14 MC1A.1 | length 2926.4
  L1-TOP w4.2: MC1.14@3061.04,1315.37 3061.04,1284.73 3064.58,1281.18 3064.58,1241.81 3051.9,1229.12 3051.9,1215.87 2989.57,1153.54 2660.79,1153.54 2634.49,1153.54 cw(c2634.49,1158.38) 2629.65,1158.38 2629.65,1163.69 ccw(c2624.81,1163.69) 2624.81,1168.53 2610.29,1168.53 ccw(c2610.29,1163.69) 2605.45,1163.69 2605.45,1158.38 cw(c2600.61,1158.38) 2600.61,1153.54 2586.09,1153.54 cw(c2586.09,1158.38) 2581.25,1158.38 2581.25,1163.69 ccw(c2576.41,1163.69) 2576.41,1168.53 2561.89,1168.53 ccw(c2561.89,1163.69) 2557.05,1163.69 2557.05,1158.38 cw(c2552.21,1158.38) 2552.21,1153.54 2537.69,1153.54 cw(c2537.69,1158.38) 2532.85,1158.38 2532.85,1162.52 ccw(c2528.01,1162.52) 2528.01,1167.36 2513.49,1167.36 ccw(c2513.49,1162.52) 2508.65,1162.52 2508.65,1158.38 cw(c2503.81,1158.38) 2503.81,1153.54 2477.79,1153.54 2463.45,1153.54 2358.27,1258.73 2358.27,1874.02 2566.93,2082.68 3500,2082.68 3537.01,2119.68 3588.98,2119.68 MC1A.1@3622.05,2086.61
pads on no net: FID1.FID? FID2.FID? FID3.FID? FID4.FID? FID5.FID? FID6.FID? FID7.FID? FID8.FID? J1.1@1181.1,2755.91 J1.1@2519.69,2755.91 J1.37 J1.38 J1.MH J2.1@3031.5,2755.91 J2.1@4370.08,2755.91 J2.37 J2.38 J2.MH J3.12 J3.14 J4.1@787.45,-2755.91 J4.1@2126.03,-2755.91 J4.37 J4.38 J4.MH J5.1@2637.84,-2755.91 J5.1@3976.43,-2755.91 J5.37 J5.38 J5.MH J8.1@7050.89,2756.02 J8.1@8539.87,2756.02 J8.37 J8.38 J8.MH J23.1@5003.65,2756.02 J23.1@6492.63,2756.02 J23.37 J23.38 J23.MH J24.0 J26.MH J27.MH J28.3 J30.MH J31.MH J32.6 J32.8 J32.20 J32.22 J32.24 J32.26 J32.28 J32.30 J32.32 J32.34 J32.36 J32.46 J32.48 J32.56 J32.58 J32.67 J32.MH JSO1.1 JSO2.1 JSO3.1 JSO4.1 MC1.119 MC1.120 MC1.131 MC1.132 MC1.137 MC1.138 MC1.139 MC1.141 MC1.143 MC1.145 MC1.147 MC1.148 MC1.149 MC1.150 MC1.161 MC1.162 MC1.163 MC1.164 MC1.165 MC1.166 MC1.167 MC1.168 MC1.169 MC1.170 MC1.171 MC1.172 MC1.180 MC1.MH MC2.24 MC2.26 MC2.135 MC2.136 MC2.178 MC2.180 MC2.MH MC3.17 MC3.19 MC3.105 MC3.106 MC3.107 MC3.108 MC3.109 MC3.110 MC3.111 MC3.112 MC3.MH MH1.1 MH2.1 MH5.1 MH6.1 MH7.1 MH8.1 QSFP1.0 QSFP2.0 U2.2 U2.5 U2.6 U2.10 U2.12 U2.17 U2.18 U2.20 U3.13 U3.27 U3.34 U3.41 U3.44 U3.48 U4.5 U4.6 U4.9 U4.10 U5.6 U5.9 U8.6 U8.9 U9.6 U9.9 U11.6 U11.9 U12.5 U12.6 U12.9 U12.10
copper on no net:
  other v1: 3086.61,-2472.44 3016.67,-2457.47 3377.95,-1511.39 3139.61,1200.98 3178.98,1200.98 3218.36,1200.98 3159.63,1240.35 3199,1240.35 3238.37,1240.35 3283.48,1393.7 3360.38,1393.7 3438.04,1393.7 3505.94,2583.05 3568.94,2583.05 3631.94,2583.05

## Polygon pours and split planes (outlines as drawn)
DGND on L5-PWR "L4-DGND" (solid, pour order 307): 19.68,-2932.76 19.68,2932.74 9428.8,2932.74 9428.8,-2932.76
VIO2 on L5-PWR "VIO2_L05_P302" (solid, pour order 302): 1755.91,-2289.72 1692.91,-2289.72 1692.91,-2932.76 8191.31,-2932.76 8191.31,-2755.91 7344.38,-1908.99 7344.38,1143.6 7905.51,1704.72 8584.65,1704.72 9090.55,2210.63 9090.55,2500 8870.08,2500 8629.92,2259.84 7566.93,2259.84 6389.76,1082.68 6389.76,-532.93 5405.05,-1517.65 2965.65,-1517.65 2811.35,-1517.65 2344.75,-1984.25 1755.91,-1984.25
+VDCIN on L5-PWR "L6_+VDCIN" (solid, pour order 306): 0,2952.75 0,-2275.59 1740.16,-2275.59 1740.16,-216.54 2976,1019.31 2976,1525.8 2976,1709.04 2648.12,2036.92 2648.12,2155.83 2071.5,2732.44 2071.5,2952.75
VIO1 on L5-PWR "VIO1_L05_P301" (solid, pour order 301): 1444.88,2251.97 1972.44,1724.41 3877.95,1724.41 4601.38,1000.98 4956.69,1000.98 5000,1044.29 5000,1669.29 5137.8,1807.09 5610.24,1807.09 6106.3,2303.15 7188.98,2303.15 7559.06,2673.23 7559.06,2933.24 1444.88,2933.24
+3.3V_M.2 on L5-PWR "+3.3V_M.2_L05_P299" (solid, pour order 299): 2334.65,-1972.44 2804.73,-1502.35 5403.16,-1502.35 5799.21,-1106.3 5929.67,-1106.3 5980.32,-1156.95 5980.32,-1557.06 6120.1,-1696.85 6181.5,-1696.85 6199.68,-1678.66 6199.68,-1368.97 6141.84,-1311.13 6141.73,-1161.42 6201.38,-1106.88 6199.68,-965.67 6350.39,-814.96 6350.39,43.31 6271.65,122.05 2098.43,122.05 1755.91,-220.47 1755.91,-1972.44
VDDD on L5-PWR "L6_VDDD" (solid, pour order 304): 1172.98,-1746.28 1209.98,-1746.28 1356.25,-1892.56 1356.25,-2381.28 1068.98,-2381.28 1068.98,-1988.6 1172.98,-1884.6
+VDCIN on L1-TOP "NONET_L-01_P-001" (solid, pour order 339): 1051.18,2212.6 826.77,2212.6 783.46,2255.91 783.46,2555.12 732.28,2606.3 488.19,2606.3 279.53,2397.64 279.53,1645.67 354.33,1570.87 1051.18,1570.87
+1.8VDD on L1-TOP "+1.8VDD_L01_P328" (solid, pour order 328): 5061.13,1598.43 5053.73,1598.43 5053.73,1618.35 5073.17,1637.8 5114.59,1637.8 5129.92,1622.47 5129.92,1502.75 5061.13,1502.75
VIO2 on L1-TOP "NONET_L-01_P-001" (solid, pour order 335): 2972.34,-1511.7 2952.77,-1492.13 2901.57,-1492.13 2881.89,-1511.81 2881.89,-1610.24 2901.57,-1629.92 2948.82,-1629.92 2972.34,-1606.4
+VDCIN on L1-TOP "+VDCIN_L01_P331" (solid, pour order 331): 2798.92,1633.57 2977.11,1633.57 3007.89,1602.79 3007.89,1248.05 2968.5,1208.66 2759.84,1208.66 2740.16,1228.35 2740.16,1574.8
VIO1 on L1-TOP "NONET_L-01_P-001" (solid, pour order 334): 5023.64,1343.91 5055.13,1343.91 5055.13,1275.59 5062.99,1267.73 5062.99,1200.79 4870.08,1007.87 4740.16,1007.87 4728.35,1019.68 4728.35,1083.66 4739.17,1094.49 4842.54,1094.49 5023.64,1275.59 5023.64,1286.83
DGND on L1-TOP "DGND_L01_P332" (solid, pour order 332): 5911.42,-66.93 5988.19,-66.93 6043.31,-66.93 6051.18,-74.8 6051.18,-114.17 6043.31,-122.05 5996.06,-122.05 5992.13,-118.11 5911.42,-118.11
NetC104_2 on L1-TOP "NETC104_2_L01_P319" (solid, pour order 319): 6486.19,2014.66 6564.93,2014.66 6578.71,2000.88 6578.71,1874.9 6559.02,1855.21 6488.16,1855.21 6488.16,1911.31 6501.94,1925.09 6501.94,1959.54 6486.19,1975.29
NetC92_2 on L1-TOP "NETC92_2_L01_P323" (solid, pour order 323): 6486.2,991.04 6564.94,991.04 6578.72,977.26 6578.72,851.28 6559.04,831.59 6488.17,831.59 6488.17,887.69 6501.95,901.47 6501.95,935.92 6486.2,951.67
+3.3V_M.2 on L1-TOP "+3.3V_M.2_L01_P330" (solid, pour order 330): 6171.88,-846.46 6307.09,-846.46 6326.77,-826.77 6326.77,-762.58 6171.88,-762.58
+3.3V_M.2 on L1-TOP "+3.3V_M.2_L01_P329" (solid, pour order 329): 6171.88,-27.56 6307.09,-27.56 6326.77,-47.24 6326.77,-129.92 6171.88,-129.92
NetC106_2 on L1-TOP "NETC106_2_L01_P320" (solid, pour order 320): 6630.87,2014.66 6707.65,2014.66 6721.43,2000.88 6721.43,1874.9 6701.74,1855.21 6630.87,1855.21 6630.87,1911.31 6630.87,1973.32
NetC102_2 on L1-TOP "NETC102_2_L01_P321" (solid, pour order 321): 6769.65,2014.66 6846.43,2014.66 6860.2,2000.88 6860.2,1874.9 6840.52,1855.21 6769.65,1855.21 6769.65,1911.31 6769.65,1973.32
+3.3V_QSFP on L1-TOP "+3.3V_QSFP_L01_P322" (solid, pour order 322): 6486.19,2046.16 6848.39,2046.16 6848.39,2094.39 6862.17,2108.17 6862.17,2168.2 6833.63,2196.75 6584.61,2196.75 6568.87,2181 6568.87,2132.77 6544.26,2108.17 6499.97,2108.17 6486.19,2094.39
NetC94_2 on L1-TOP "NETC94_2_L01_P324" (solid, pour order 324): 6630.89,991.04 6707.66,991.04 6721.44,977.26 6721.44,851.28 6701.76,831.59 6630.89,831.59 6630.89,887.69 6630.89,949.7
NetC90_2 on L1-TOP "NETC90_2_L01_P325" (solid, pour order 325): 6769.67,991.04 6846.44,991.04 6860.22,977.26 6860.22,851.28 6840.54,831.59 6769.67,831.59 6769.67,887.69 6769.67,949.7
+3.3V_QSFP on L1-TOP "+3.3V_QSFP_L01_P326" (solid, pour order 326): 6486.2,1022.54 6848.41,1022.54 6848.41,1070.76 6862.19,1084.54 6862.19,1144.58 6833.65,1173.13 6584.63,1173.13 6568.88,1157.38 6568.88,1109.15 6544.28,1084.54 6499.98,1084.54 6486.2,1070.76
+3.3V_SZG on L6-PWR "+3.3V_SZG_L06_P318" (solid, pour order 318): 19.69,2933.07 9429.13,2933.07 9429.13,-2933.07 19.69,-2933.07
+3.3V_QSFP on L6-PWR "+3.3V_QSFP_L06_P316" (solid, pour order 316): 1811.02,-2259.84 6598.43,-2259.84 8149.61,-708.66 8149.61,1314.96 8913.39,2078.74 9094.49,2078.74 9094.49,2480.32 8177.17,2480.32 8177.17,2244.09 6417.32,2244.09 4066.93,-106.3 3279.53,-106.3 1811.02,-1574.8
NetC94_2 on L6-PWR "NETC94_2_L06_P315" (solid, pour order 315): 7144.7,466.76 7144.7,389.64 6784.48,389.64 6574.8,599.32 6574.8,903.44 6755.9,903.44 6755.9,679.03 6968.16,466.76
NetC90_2 on L6-PWR "NETC90_2_L06_P314" (solid, pour order 314): 7139.48,476.38 7139.48,531.94 7279.51,531.94 7279.51,903.44 6768.69,903.44 6768.69,684.08 6976.39,476.38
NetC92_2 on L6-PWR "NETC92_2_L06_P313" (solid, pour order 313): 7143.7,520.94 7279.51,520.94 7279.51,149.27 7246.28,116.04 6711.62,116.04 6393.69,433.97 6393.69,903.44 6563.97,903.44 6563.97,595.39 6769.75,389.6 7093.5,389.6 7143.7,439.8
NetC106_2 on L6-PWR "NETC106_2_L06_P312" (solid, pour order 312): 7144.69,1490.39 7144.69,1413.26 6784.46,1413.26 6574.78,1622.94 6574.78,1927.06 6755.88,1927.06 6755.88,1702.65 6968.14,1490.39
NetC102_2 on L6-PWR "NETC102_2_L06_P311" (solid, pour order 311): 7139.47,1500.01 7139.47,1555.56 7279.5,1555.56 7279.5,1927.06 6768.68,1927.06 6768.68,1707.7 6976.37,1500.01
NetC104_2 on L6-PWR "NETC104_2_L06_P310" (solid, pour order 310): 7143.69,1544.56 7279.5,1544.56 7279.49,1172.89 7246.27,1139.66 6872.15,1139.66 6834.65,1177.17 6674.1,1177.17 6393.68,1457.59 6393.68,1927.06 6563.95,1927.06 6563.95,1619.01 6769.74,1413.22 7093.48,1413.22 7143.69,1463.43
+5V_SZG on L6-PWR "+5V_SZG_L06_P317" (solid, pour order 317): 3023.62,-2692.91 2994.41,-2692.91 2865.95,-2564.45 1309.7,-2564.45 1181.24,-2692.91 1122.52,-2692.91 870.55,-2440.94 523.62,-2440.94 456.69,-2374.02 456.69,-2209.72 493.19,-2173.23 640.57,-2173.23 1011.81,-1801.99 1011.81,1580.02 2124.71,2692.91 2170,2692.91 2279.46,2583.45 3858.45,2583.45 3967.91,2692.91 4016.93,2692.91 4156.39,2553.45 5882.64,2553.45 6022.08,2692.9 6094.41,2692.9 6233.85,2553.45 7927.47,2553.45 8066.9,2692.88 8161.42,2692.88 8161.42,2259.84 7919.57,2259.84 6409.45,2259.84 5129.87,980.26 3106.3,-1043.31 3106.3,-2610.24
DGND on L3-SIG "NONET_L-01_P-001" (solid, pour order 336): 8948.82,27.56 9448.82,27.56 9448.82,-2952.76 7728.35,-2952.76 7728.35,-2598.43 7641.73,-2511.81 5759.84,-2511.81 5165.35,-1917.32 4858.27,-1917.32 4720.47,-1779.53 4720.47,-1377.95 4767.72,-1330.71 5326.77,-1330.71 5816.93,-1820.87 6143.7,-1820.87 6547.24,-1417.32 6547.24,-216.54 6342.52,-11.81 6139.76,-11.81 6055.12,-96.46 6055.12,-811.02 5960.63,-905.51 5279.53,-905.51 4925.2,-551.18 4925.2,468.5 5255.91,799.21 5622.05,799.21 5622.05,834.65 6118.11,1330.71 6893.7,1330.71 7102.36,1122.05 7102.36,767.72 7098.43,767.72 6905.51,574.8 6905.51,469.32 7032.31,342.52 8948.82,342.52
DGND on L3-SIG "NONET_L-01_P-001" (solid, pour order 333): 0,-1484.25 311.02,-1484.25 311.02,-338.58 1834.65,1185.04 3389.76,1185.04 3389.76,1625.98 3503.94,1740.16 3503.94,2271.65 5125.98,2271.65 5125.98,2952.76 0,2952.76
DGND on L3-SIG "L3-SIG-DGND" (solid, pour order 338): 4429.13,539.37 4728.35,838.58 4728.35,1074.8 3724.41,1074.8 3614.17,964.57 1874.02,964.57 480.32,-429.13 480.32,-2263.78 267.72,-2476.38 0,-2476.38 0,-2952.76 929.13,-2952.76 929.13,-2397.64 1145.67,-2181.1 1263.78,-2181.1 1295.28,-2212.6 1295.28,-2358.27 1125.98,-2527.56 1125.98,-2771.65 4216.54,-2771.65 4216.54,-2338.58 3374.02,-1496.06 2933.07,-1496.06 2570.87,-1858.27 2570.87,-2149.61 2515.75,-2204.72 2385.83,-2204.72 2330.71,-2149.61 2330.71,-1881.89 2578.74,-1633.86 2578.74,-1118.11 4429.13,-1118.11
DGND on L8-BOT "DGND_L08_P309" (solid, pour order 309): 481.62,-1940.41 481.62,-2184.8 581.33,-2184.8 631.94,-2235.41 1314.6,-2235.41 1314.6,-1940.41
DGND on L4-GND "DGND_L04_P300" (solid, pour order 300): 19.69,-2933.07 19.69,2933.07 9429.13,2933.07 9429.13,-2933.07
DGND on L2-GND "DGND_L02_P303" (solid, pour order 303): 19.68,-2932.76 19.68,2932.74 9428.8,2932.74 9428.8,-2932.76
DGND on L7-GND "DGND_L07_P308" (solid, pour order 308): 19.69,-2933.07 9429.13,-2933.07 9429.13,2933.07 19.69,2933.07

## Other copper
L1-TOP:
  region net +3.3V_SZG: 7534.94,2686.87 7502.94,2686.87 7502.94,2598.87 7534.94,2598.87
  region net +3.3V_SZG: 5487.69,2686.87 5455.69,2686.87 5455.69,2598.87 5487.69,2598.87
  rectangle net +5V_SZG: 8075.61,2599.19 8107.61,2687.19
  region net VIO1: 7534.94,2912.86 7502.94,2912.86 7502.94,2824.86 7534.94,2824.86
  region net VIO1: 5487.69,2912.86 5455.69,2912.86 5455.69,2824.86 5487.69,2824.86
  rectangle net +5V_SZG: 6028.37,2599.19 6060.37,2687.19
  region net DGND: 481.62,-2007.66 481.62,-2128.66 624.73,-2128.66 646.23,-2107.16 843.74,-2107.16 843.74,-2135.16 921.74,-2135.16 921.74,-2060.16 933.74,-2048.16 971.74,-2048.16 971.74,-2023.16 816.74,-2023.16 816.74,-2028.41 644.85,-2028.41 624.1,-2007.66
  region net DGND: 1331.74,-2076.16 1331.74,-2048.16 1360.74,-2048.16 1421.74,-1987.16 1484.74,-1987.16 1528.16,-2030.58 1774.74,-2030.58 1774.74,-2009.66 1997.74,-2009.66 1997.74,-2129 1774.74,-2129 1774.74,-2104.45 1509.74,-2104.45 1509.74,-2076.16
  region net +VDCIN: 935.74,-2136.66 1012.74,-2136.66 1051.24,-2098.16 1093.74,-2098.16 1093.74,-2067.16 1052.74,-2067.16 1008.74,-2023.16 983.74,-2023.16 983.74,-2062.16 935.74,-2062.16
  region net +VDCIN: 1331.74,-2089.16 1331.74,-2117.16 1365.74,-2117.16 1418.74,-2170.16 1496.47,-2170.16 1496.47,-2089.16
  region net +3.3V_SZG: 481.62,-1863.54 481.62,-1990.54 697.92,-1990.54 718.41,-2011.03 781.29,-2011.03 781.29,-1839.94 594.51,-1839.94 570.92,-1863.54
  region net +VDCIN: 1063.1,-1802.16 1063.1,-1851.16 1080.74,-1851.16 1105.74,-1876.16 1105.74,-1903.49 1121.17,-1903.49 1138.1,-1920.41 1138.1,-1964.16 1149.1,-1964.16 1149.1,-1892.02 1139.74,-1882.66 1139.74,-1802.16
  region net NetC56_2: 1094.74,-2058.16 1059.24,-2058.16 1008.74,-2007.66 822.98,-2007.66 822.98,-1844.07 884.88,-1844.07 901.74,-1860.93 901.74,-1972.16 913.74,-1984.16 1002.77,-1984.16 1066.77,-2048.16 1094.74,-2048.16
  region net NetC45_2: 1581.74,-2016.16 1581.74,-1802.16 1547.24,-1802.16 1484.74,-1864.66 1484.74,-1942.66 1406.74,-1942.66 1360.24,-1989.16 1331.74,-1989.16 1331.74,-2033.45 1357.74,-2033.45 1420.53,-1970.66 1495.24,-1970.66 1540.74,-2016.16
  region net NetC35_2: 1331.74,-2127.16 1360.24,-2127.16 1418.24,-2185.16 1509.74,-2185.16 1509.74,-2120.16 1583.47,-2120.16 1583.47,-2333.16 1542.74,-2333.16 1474.74,-2265.16 1474.74,-2224.16 1410.24,-2224.16 1362.24,-2176.16 1331.74,-2176.16
  region net +3.3V_M.2: 2010.74,-1882.16 2010.74,-1997.66 1723.47,-1997.66 1723.47,-1807.16 1775.09,-1807.16 1850.09,-1882.16
  pour cut-out: 1098.57,-1964.55 1326.92,-1964.55 1330.85,-1968.49 1330.85,-2196.84 1326.92,-2200.77 1098.57,-2200.77 1094.63,-2196.84 1094.63,-1968.49
  region net +5V_SZG: 481.62,-2266.54 481.62,-2139.54 697.92,-2139.54 759.77,-2139.54 779.19,-2158.95 779.19,-2328.73 710.77,-2328.73 670.81,-2288.76 593.14,-2288.76 570.92,-2266.54
  region net +3.3V_QSFP: 2010.74,-2140.16 1757.74,-2140.16 1757.74,-2120.16 1708.74,-2120.16 1707.74,-2119.16 1707.74,-2332.16 1769.09,-2332.16 1846.1,-2255.16 2010.74,-2255.16
  region net NetC66_2: 1093.74,-2107.16 1055.74,-2107.16 1013.74,-2149.16 828.74,-2149.16 822.98,-2149.16 822.98,-2322.37 878.53,-2322.37 902.74,-2298.16 902.74,-2190.66 916.24,-2177.16 1006.24,-2177.16 1066.24,-2117.16 1093.74,-2117.16

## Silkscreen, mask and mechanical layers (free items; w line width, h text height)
Top Overlay:
  circle w22: c816.45,2756.65 r11
  rectangle: 4673.65,-2511.81 5334.65,-2196.85
  lines w4.72: 6250,-870.08 6250,-870.01 9230.39,-870.01 9230.39,-608.01 ; 6250,-3.94 9230.39,-3.94 9230.39,-265.01 ; 7261.39,-870.01 7261.39,-608.01 ; 7261.39,-265.94 7261.39,-3.94 ; 7734.39,-870.01 7734.39,-608.01 ; 7734.39,-265.94 7734.39,-3.94 ; 8442.39,-870.01 8442.39,-608.01 ; 8443.39,-265.94 8443.39,-3.94
  lines w7.87: 413.39,-1673.23 5708.68,-1673.21 5708.68,1673.24 413.39,1673.23
  lines w15.75: 778.86,2770.33 ccw(c816.45,2756.65) 854.04,2770.33 ; 816.45,2668.65 816.45,2716.65 ; 816.45,2756.65 816.45,2818.65
  lines w20: 7156.22,-1977.94 8179.84,-1977.94 8179.84,-953.57 7156.22,-953.57 7156.22,-1977.94 ; 7744.09,-2879.92 7744.09,-2574.8 8708.66,-2574.8 9082.68,-2574.8 9082.68,-2879.92 7744.09,-2879.92 ; 7744.09,-2446.85 7744.09,-2141.73 8688.98,-2141.73 9082.68,-2141.73 9082.68,-2446.85 7744.09,-2446.85 ; 8337.32,-1977.94 9360.94,-1977.94 9360.94,-953.57 8337.32,-953.57 8337.32,-1977.94
  text "+" at 777.45,2831.65 h70
  text "-" at 851.44,2576.66 h70 r90
  text "6-16 VDC" at 350.39,2362.2 h100
  text "DGND" at 3460.1,1991.54 h30
  text "PWR" at 397.64,1704.72 h60
  text "GND" at 574.8,1704.72 h60
  text "M.2" at 6028.64,35.43 h100
  text "2230" at 7248.02,-222.43 h100 r90
  text "2242" at 7720.02,-222.43 h100 r90
  text "2260" at 8429.02,-222.43 h100 r90
  text "2280" at 9216.02,-222.43 h100 r90
  text "SMA 227" at 8210.46,-1269.11 h100 r270
  text "SATA 1" at 6509.52,-1457.39 h100
  text "JTAG" at 295.98,-1779.53 h100 r270
  text "SATA 2" at 6504.92,-1968.9 h100
  text "'.Part_Number' / '.PCB_Revision'XX" at 4975.64,-2091.79 h40
  text "10:TDI" at 303.15,-2096.45 h30
  text "8:TDO" at 303.15,-2175.45 h30
  text "6:TCK" at 303.15,-2252.45 h30
  text "4:TMS" at 303.15,-2331.45 h30
  text "2:Vref" at 303.15,-2409.45 h30
  text "U.FL 224" at 8210.06,-2552.51 h100
  text "DGND" at 5909.45,-2854.33 h30
Dimensions:
  text ":::" at 3719.7,3025.47 h50 r180
  text ":::" at 7501.7,2982.24 h50
  text ":::" at 9501.47,1157.24 h50 r270
  text ":::" at -41,1110 h50 r90
  text ":::" at -53,-1222 h50 r90
  text ":::" at 9501.47,-2410.76 h50 r270
  text ":::" at 2816,-2993 h50 r180
  text ":::" at 6897,-3016 h50 r180
Outline:
  the board outline again, w7.87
